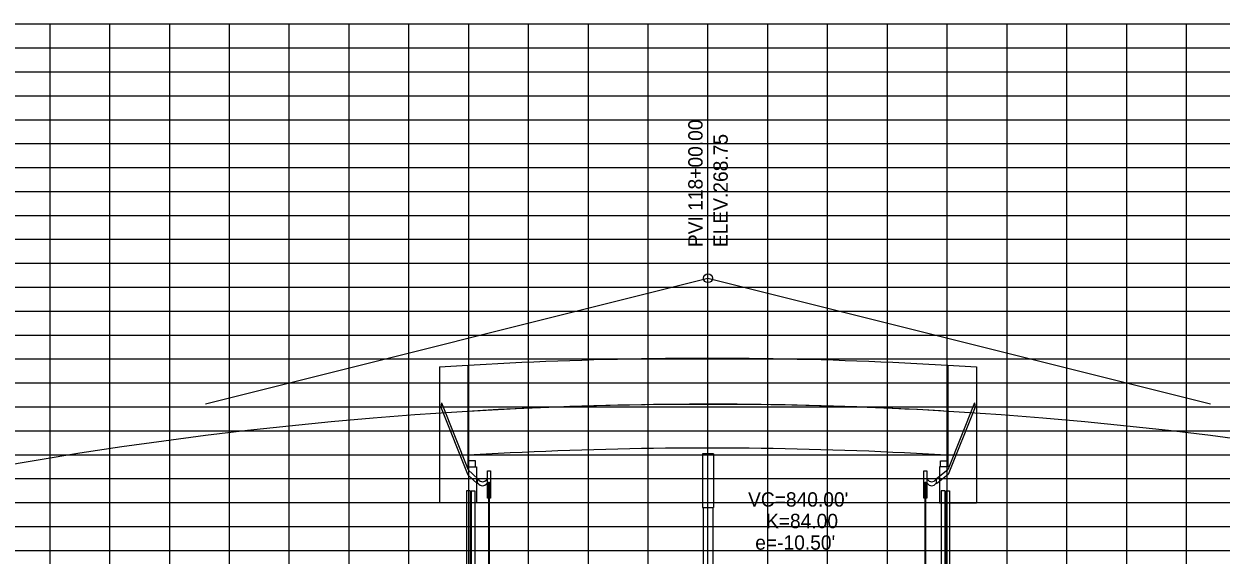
# Model space of a CAD drawing. Extents: x 921603 to 924670, y 1759276 to 1766491.
# Drawn here: x 923154 to 923654, y 1765310 to 1765532 of the extents above; entities that cross this region are included whole.
import ezdxf

# ---------------------------------------------------------------- set-up
doc = ezdxf.new("R2010")
doc.units = 0
for name, color, linetype in [('B-Gen-Exist', 7, 'Continuous'), ('B-Gen-Hidden', 7, 'Continuous'), ('B-Gen-Object', 7, 'Continuous'), ('B-Sub-Retaining Wall', 7, 'Continuous'), ('R_Grid', 7, 'Continuous'), ('R_Grid_Minor', 7, 'Continuous'), ('R_Vert Alg', 7, 'Continuous'), ('R_Vert Alg Annot', 7, 'Continuous')]:
    doc.layers.add(name, color=color, linetype=linetype)

msp = doc.modelspace()

# ---------------------------------------------------------------- linework, layer by layer
at = {"layer": 'B-Gen-Exist'}
for p, q in [((923339.69, 1765389.67), (923339.69, 1765368.36)), ((923539.97, 1765389.68), (923539.97, 1765378.37))]:
    msp.add_line(p, q, dxfattribs=at)
at = {"layer": 'B-Gen-Hidden'}
for p, q in [((923340.35, 1765337.18), (923338.85, 1765337.18)), ((923338.85, 1765337.18), (923338.85, 1765087.18)), ((923340.35, 1765337.18), (923340.35, 1765087.18)), ((923340.85, 1765337.18), (923340.85, 1765087.18)), ((923340.85, 1765337.18), (923342.35, 1765337.18)), ((923342.35, 1765337.18), (923342.35, 1765087.18)), ((923538.8, 1765337.18), (923537.3, 1765337.18)), ((923537.3, 1765337.18), (923537.3, 1765087.18)), ((923538.8, 1765337.18), (923538.8, 1765087.18)), ((923539.3, 1765337.18), (923539.3, 1765087.18)), ((923539.3, 1765337.18), (923540.8, 1765337.18)), ((923540.8, 1765337.18), (923540.8, 1765087.18))]:
    msp.add_line(p, q, dxfattribs=at)
at = {"layer": 'B-Gen-Object'}
for p, q in [((923327.6, 1765388.93), (923337.04, 1765389.52)), ((923337.04, 1765389.52), (923339.6, 1765389.67)), ((923339.6, 1765347.18), (923339.6, 1765389.67)), ((923339.77, 1765389.68), (923342.04, 1765389.82)), ((923339.77, 1765389.68), (923339.77, 1765352.18)), ((923342.04, 1765389.82), (923347.04, 1765390.1)), ((923347.05, 1765390.1), (923352.05, 1765390.37)), ((923352.05, 1765390.37), (923357.05, 1765390.62)), ((923357.05, 1765390.62), (923362.05, 1765390.86)), ((923362.05, 1765390.86), (923367.05, 1765391.08)), ((923367.05, 1765391.08), (923372.05, 1765391.29)), ((923372.05, 1765391.29), (923377.05, 1765391.49)), ((923377.06, 1765391.49), (923382.06, 1765391.67)), ((923382.06, 1765391.67), (923387.06, 1765391.83)), ((923387.06, 1765391.83), (923392.06, 1765391.98)), ((923392.06, 1765391.98), (923397.06, 1765392.12)), ((923397.06, 1765392.12), (923402.06, 1765392.24)), ((923402.07, 1765392.24), (923407.07, 1765392.34)), ((923407.07, 1765392.34), (923412.07, 1765392.43)), ((923412.07, 1765392.43), (923417.07, 1765392.51)), ((923417.07, 1765392.51), (923422.07, 1765392.57)), ((923422.07, 1765392.57), (923427.07, 1765392.61)), ((923427.07, 1765392.61), (923432.07, 1765392.64)), ((923432.08, 1765392.64), (923437.08, 1765392.66)), ((923437.08, 1765392.66), (923442.08, 1765392.66)), ((923442.08, 1765392.66), (923447.08, 1765392.64)), ((923447.08, 1765392.64), (923452.08, 1765392.62)), ((923452.08, 1765392.62), (923457.08, 1765392.57)), ((923457.08, 1765392.57), (923462.08, 1765392.51)), ((923462.09, 1765392.51), (923467.09, 1765392.44)), ((923467.09, 1765392.44), (923472.09, 1765392.35)), ((923472.09, 1765392.35), (923477.09, 1765392.25)), ((923477.09, 1765392.25), (923482.09, 1765392.13)), ((923482.09, 1765392.13), (923487.09, 1765392)), ((923487.1, 1765392), (923492.1, 1765391.85)), ((923492.1, 1765391.85), (923497.1, 1765391.68)), ((923497.1, 1765391.68), (923502.1, 1765391.51)), ((923502.1, 1765391.51), (923507.1, 1765391.31)), ((923507.1, 1765391.31), (923512.1, 1765391.11)), ((923512.1, 1765391.11), (923517.1, 1765390.88)), ((923517.11, 1765390.88), (923522.11, 1765390.65)), ((923522.11, 1765390.65), (923527.11, 1765390.39)), ((923527.11, 1765390.39), (923532.11, 1765390.13)), ((923532.11, 1765390.13), (923539.88, 1765389.69)), ((923539.88, 1765389.69), (923539.88, 1765352.18)), ((923540.05, 1765389.68), (923552.05, 1765389)), ((923540.05, 1765389.68), (923540.05, 1765347.18)), ((923327.6, 1765388.93), (923327.6, 1765332.18)), ((923552.05, 1765389), (923552.05, 1765332.18)), ((923328.39, 1765373.96), (923328.2, 1765372.1)), ((923328.2, 1765372.1), (923339.48, 1765343.9)), ((923328.39, 1765373.96), (923339.6, 1765345.93)), ((923339.77, 1765370.51), (923342.09, 1765370.65)), ((923342.09, 1765370.65), (923347.09, 1765370.93)), ((923347.09, 1765370.93), (923352.09, 1765371.2)), ((923352.09, 1765371.2), (923357.09, 1765371.46)), ((923357.09, 1765371.46), (923362.09, 1765371.69)), ((923362.09, 1765371.69), (923367.08, 1765371.92)), ((923367.08, 1765371.92), (923372.08, 1765372.13)), ((923372.08, 1765372.13), (923377.08, 1765372.32)), ((923377.08, 1765372.32), (923382.08, 1765372.5)), ((923382.08, 1765372.5), (923387.08, 1765372.67)), ((923387.08, 1765372.67), (923392.08, 1765372.81)), ((923392.08, 1765372.81), (923397.08, 1765372.95)), ((923397.08, 1765372.95), (923402.08, 1765373.07)), ((923402.08, 1765373.07), (923407.08, 1765373.17)), ((923407.08, 1765373.17), (923412.08, 1765373.26)), ((923412.08, 1765373.26), (923417.08, 1765373.34)), ((923417.08, 1765373.34), (923422.08, 1765373.4)), ((923422.08, 1765373.4), (923427.08, 1765373.44)), ((923427.08, 1765373.44), (923432.08, 1765373.48)), ((923432.08, 1765373.48), (923437.08, 1765373.49)), ((923437.08, 1765373.49), (923442.08, 1765373.49)), ((923442.08, 1765373.49), (923447.08, 1765373.48)), ((923447.08, 1765373.48), (923452.08, 1765373.45)), ((923452.08, 1765373.45), (923457.08, 1765373.4)), ((923457.08, 1765373.4), (923462.08, 1765373.35)), ((923462.08, 1765373.35), (923467.07, 1765373.27)), ((923467.07, 1765373.27), (923472.07, 1765373.18)), ((923472.07, 1765373.18), (923477.07, 1765373.08)), ((923477.07, 1765373.08), (923482.07, 1765372.96)), ((923482.07, 1765372.96), (923487.07, 1765372.83)), ((923487.07, 1765372.83), (923492.07, 1765372.68)), ((923492.07, 1765372.68), (923497.07, 1765372.52)), ((923497.07, 1765372.52), (923502.07, 1765372.34)), ((923502.07, 1765372.34), (923507.07, 1765372.15)), ((923507.07, 1765372.15), (923512.07, 1765371.94)), ((923512.07, 1765371.94), (923517.07, 1765371.72)), ((923517.07, 1765371.72), (923522.07, 1765371.48)), ((923522.07, 1765371.48), (923527.07, 1765371.23)), ((923527.07, 1765371.23), (923532.07, 1765370.96)), ((923532.07, 1765370.96), (923537.07, 1765370.68)), ((923537.07, 1765370.68), (923539.88, 1765370.51)), ((923551.27, 1765373.96), (923540.05, 1765345.93)), ((923551.45, 1765372.1), (923540.18, 1765343.92)), ((923551.27, 1765373.96), (923551.45, 1765372.1)), ((923342.6, 1765349.68), (923339.6, 1765349.68)), ((923342.6, 1765347.18), (923342.6, 1765349.68)), ((923442.08, 1765352.66), (923437.58, 1765352.66)), ((923437.58, 1765352.66), (923437.58, 1765330.16)), ((923442.08, 1765352.66), (923442.08, 1765330.16)), ((923537.05, 1765347.18), (923537.05, 1765349.68)), ((923537.05, 1765349.68), (923540.05, 1765349.68)), ((923339.6, 1765347.18), (923343.1, 1765347.18)), ((923339.6, 1765345.93), (923343.6, 1765342.18)), ((923343.1, 1765347.18), (923343.1, 1765332.18)), ((923540.05, 1765345.93), (923535.31, 1765342.18)), ((923540.05, 1765347.18), (923536.55, 1765347.18)), ((923536.55, 1765347.18), (923536.55, 1765332.18)), ((923339.48, 1765343.9), (923343.52, 1765340.14)), ((923343.52, 1765340.14), (923343.52, 1765342.25)), ((923540.18, 1765343.92), (923535.31, 1765340.07)), ((923535.31, 1765340.07), (923535.31, 1765342.18)), ((923343.1, 1765332.18), (923327.6, 1765332.18)), ((923437.58, 1765330.16), (923442.08, 1765330.16)), ((923437.83, 1765330.16), (923437.83, 1765282.66)), ((923441.84, 1765330.16), (923441.84, 1765282.66)), ((923536.55, 1765332.18), (923552.05, 1765332.18))]:
    msp.add_line(p, q, dxfattribs=at)
msp.add_lwpolyline([(923339.77, 1765352.18), (923342.13, 1765352.32), (923347.13, 1765352.6), (923352.12, 1765352.87), (923357.12, 1765353.12), (923362.12, 1765353.36), (923367.12, 1765353.59), (923372.11, 1765353.79), (923377.11, 1765353.99), (923382.11, 1765354.17), (923387.11, 1765354.33), (923392.1, 1765354.48), (923397.1, 1765354.62), (923402.1, 1765354.74), (923407.1, 1765354.84), (923412.09, 1765354.93), (923417.09, 1765355.01), (923422.09, 1765355.07), (923427.08, 1765355.11), (923432.08, 1765355.14), (923437.08, 1765355.16), (923442.08, 1765355.16), (923447.07, 1765355.14), (923452.07, 1765355.12), (923457.07, 1765355.07), (923462.07, 1765355.01), (923467.06, 1765354.94), (923472.06, 1765354.85), (923477.06, 1765354.75), (923482.06, 1765354.63), (923487.05, 1765354.5), (923492.05, 1765354.35), (923497.05, 1765354.18), (923502.04, 1765354.01), (923507.04, 1765353.81), (923512.04, 1765353.61), (923517.04, 1765353.38), (923522.03, 1765353.15), (923527.03, 1765352.9), (923532.03, 1765352.63), (923537.03, 1765352.35), (923539.88, 1765352.18)], dxfattribs=at)
for centre, major_axis, start_param, end_param in [((923337.08, 1765374.52), (0, 15), 0.011919, 0.012542), ((923342.08, 1765374.82), (0, 15), 0.011334, 0.011919), ((923347.08, 1765375.1), (0, 15), 0.010748, 0.011334), ((923352.08, 1765375.37), (0, 15), 0.010165, 0.010748), ((923357.08, 1765375.62), (0, 15), 0.009541, 0.010165), ((923362.08, 1765375.86), (0, 15), 0.008951, 0.009541), ((923367.08, 1765376.08), (0, 15), 0.008364, 0.008951), ((923372.08, 1765376.29), (0, 15), 0.007778, 0.008364), ((923377.08, 1765376.49), (0, 15), 0.007172, 0.007778), ((923382.08, 1765376.67), (0, 15), 0.006567, 0.007172), ((923387.08, 1765376.83), (0, 15), 0.005981, 0.006567), ((923392.08, 1765376.98), (0, 15), 0.005394, 0.005981), ((923397.08, 1765377.12), (0, 15), 0.004804, 0.005394), ((923402.08, 1765377.24), (0, 15), 0.00418, 0.004804), ((923407.08, 1765377.34), (0, 15), 0.003597, 0.00418), ((923412.08, 1765377.43), (0, 15), 0.003011, 0.003597), ((923417.08, 1765377.51), (0, 15), 0.002426, 0.003011), ((923422.08, 1765377.57), (0, 15), 0.001802, 0.002426), ((923427.08, 1765377.61), (0, 15), 0.001214, 0.001802), ((923432.08, 1765377.64), (0, 15), 0.000627, 0.001214), ((923437.08, 1765377.66), (0, 15), 0.000041, 0.000627), ((923442.08, 1765377.66), (0, 15), 6.282617, 6.283226), ((923447.08, 1765377.64), (0, 15), 6.282015, 6.282617), ((923452.08, 1765377.62), (0, 15), 6.281429, 6.282015), ((923457.08, 1765377.57), (0, 15), 6.280842, 6.281429), ((923462.08, 1765377.51), (0, 15), 6.280245, 6.280842), ((923467.08, 1765377.44), (0, 15), 6.279632, 6.280245), ((923472.08, 1765377.35), (0, 15), 6.279045, 6.279632), ((923477.08, 1765377.25), (0, 15), 6.278459, 6.279045), ((923482.08, 1765377.13), (0, 15), 6.277872, 6.278459), ((923487.08, 1765377), (0, 15), 6.277248, 6.277872), ((923492.08, 1765376.85), (0, 15), 6.276662, 6.277248), ((923497.08, 1765376.68), (0, 15), 6.276075, 6.276662), ((923502.08, 1765376.51), (0, 15), 6.275489, 6.276075), ((923507.08, 1765376.31), (0, 15), 6.274876, 6.275489), ((923512.08, 1765376.11), (0, 15), 6.274278, 6.274876), ((923517.08, 1765375.88), (0, 15), 6.273692, 6.274278), ((923522.08, 1765375.65), (0, 15), 6.273106, 6.273692), ((923527.08, 1765375.39), (0, 15), 6.272504, 6.273106), ((923532.08, 1765375.13), (0, 15), 6.271895, 6.272504), ((923345.6, 1765381.55), (0, 42.29), 2.892883, 3.380307), ((923345.6, 1765381.55), (0, 40.62), 2.892883, 3.390303), ((923533.31, 1765381.55), (0, -40.62), 6.034475, 6.531895), ((923533.31, 1765381.55), (0, -42.29), 6.044471, 6.521899)]:
    msp.add_ellipse(centre, major_axis=major_axis, ratio=0.2, start_param=start_param, end_param=end_param, dxfattribs=at)
at = {"layer": 'B-Sub-Retaining Wall'}
for p, q in [((923347.6, 1765334.08), (923347.6, 1765345.51)), ((923347.6, 1765345.51), (923348.94, 1765345.51)), ((923348.94, 1765345.51), (923348.94, 1765334.08)), ((923529.98, 1765345.51), (923531.31, 1765345.51)), ((923529.98, 1765334.08), (923529.98, 1765345.51)), ((923531.31, 1765345.51), (923531.31, 1765334.08)), ((923348.02, 1765334.08), (923348.02, 1765340.75)), ((923348.02, 1765340.75), (923348.52, 1765340.75)), ((923348.52, 1765334.08), (923348.52, 1765340.75)), ((923530.4, 1765334.08), (923530.4, 1765340.75)), ((923530.4, 1765340.75), (923530.9, 1765340.75)), ((923530.9, 1765334.08), (923530.9, 1765340.75)), ((923348.02, 1765334.08), (923347.6, 1765334.08)), ((923348.02, 1765334.08), (923348.02, 1765230.99)), ((923348.52, 1765230.99), (923348.52, 1765334.08)), ((923348.94, 1765334.08), (923348.52, 1765334.08)), ((923530.4, 1765334.08), (923529.98, 1765334.08)), ((923530.4, 1765334.08), (923530.4, 1765230.99)), ((923530.9, 1765230.99), (923530.9, 1765334.08)), ((923531.31, 1765334.08), (923530.9, 1765334.08))]:
    msp.add_line(p, q, dxfattribs=at)
at = {"layer": 'R_Grid'}
for p, q in [((921639.83, 1765532.26), (924639.83, 1765532.26)), ((921639.83, 1765532.26), (924639.83, 1765532.26)), ((923239.83, 1764932.26), (923239.83, 1765532.26)), ((923339.83, 1764932.26), (923339.83, 1765532.26)), ((923439.83, 1764932.26), (923439.83, 1765532.26)), ((923539.83, 1764932.26), (923539.83, 1765532.26)), ((923639.83, 1764932.26), (923639.83, 1765532.26)), ((921639.83, 1765482.26), (924639.83, 1765482.26)), ((921639.83, 1765432.26), (924639.83, 1765432.26)), ((921639.83, 1765382.26), (924639.83, 1765382.26)), ((921639.83, 1765332.26), (924639.83, 1765332.26))]:
    msp.add_line(p, q, dxfattribs=at)
at = {"layer": 'R_Grid_Minor'}
for p, q in [((923164.83, 1764932.26), (923164.83, 1765532.26)), ((923189.83, 1764932.26), (923189.83, 1765532.26)), ((923214.83, 1764932.26), (923214.83, 1765532.26)), ((923264.83, 1764932.26), (923264.83, 1765532.26)), ((923289.83, 1764932.26), (923289.83, 1765532.26)), ((923314.83, 1764932.26), (923314.83, 1765532.26)), ((923364.83, 1764932.26), (923364.83, 1765532.26)), ((923389.83, 1764932.26), (923389.83, 1765532.26)), ((923414.83, 1764932.26), (923414.83, 1765532.26)), ((923464.83, 1764932.26), (923464.83, 1765532.26)), ((923489.83, 1764932.26), (923489.83, 1765532.26)), ((923514.83, 1764932.26), (923514.83, 1765532.26)), ((923564.83, 1764932.26), (923564.83, 1765532.26)), ((923589.83, 1764932.26), (923589.83, 1765532.26)), ((923614.83, 1764932.26), (923614.83, 1765532.26)), ((921639.83, 1765522.26), (924639.83, 1765522.26)), ((921639.83, 1765512.26), (924639.83, 1765512.26)), ((921639.83, 1765502.26), (924639.83, 1765502.26)), ((921639.83, 1765492.26), (924639.83, 1765492.26)), ((921639.83, 1765472.26), (924639.83, 1765472.26)), ((921639.83, 1765462.26), (924639.83, 1765462.26)), ((921639.83, 1765452.26), (924639.83, 1765452.26)), ((921639.83, 1765442.26), (924639.83, 1765442.26)), ((921639.83, 1765422.26), (924639.83, 1765422.26)), ((921639.83, 1765412.26), (924639.83, 1765412.26)), ((921639.83, 1765402.26), (924639.83, 1765402.26)), ((921639.83, 1765392.26), (924639.83, 1765392.26)), ((921639.83, 1765372.26), (924639.83, 1765372.26)), ((921639.83, 1765362.26), (924639.83, 1765362.26)), ((921639.83, 1765352.26), (924639.83, 1765352.26)), ((921639.83, 1765342.26), (924639.83, 1765342.26)), ((921639.83, 1765322.26), (924639.83, 1765322.26)), ((921639.83, 1765312.26), (924639.83, 1765312.26))]:
    msp.add_line(p, q, dxfattribs=at)
at = {"layer": 'R_Vert Alg'}
msp.add_lwpolyline([(923142.33, 1765347.17), (923159.83, 1765350.18), (923177.33, 1765353), (923194.83, 1765355.64), (923212.33, 1765358.11), (923229.83, 1765360.38), (923247.33, 1765362.48), (923264.83, 1765364.39), (923282.33, 1765366.13), (923299.83, 1765367.68), (923317.33, 1765369.04), (923334.83, 1765370.23), (923352.33, 1765371.23), (923369.83, 1765372.05), (923387.33, 1765372.69), (923404.83, 1765373.14), (923422.33, 1765373.42), (923457.33, 1765373.42), (923474.83, 1765373.14), (923492.33, 1765372.69), (923509.83, 1765372.05), (923527.33, 1765371.23), (923544.83, 1765370.23), (923562.33, 1765369.04), (923579.83, 1765367.68), (923597.33, 1765366.13), (923614.83, 1765364.39), (923632.33, 1765362.48), (923649.83, 1765360.38), (923667.33, 1765358.11)], dxfattribs=at)
at = {"layer": 'R_Vert Alg Annot'}
for p, q in [((923439.83, 1765436.01), (923439.83, 1765520.01)), ((923439.83, 1765426.01), (923439.83, 1765436.01)), ((923229.83, 1765373.51), (923439.83, 1765426.01)), ((923439.83, 1765426.01), (923649.83, 1765373.51))]:
    msp.add_line(p, q, dxfattribs=at)
msp.add_circle((923439.83, 1765426.01), 1.85, dxfattribs=at)

# ---------------------------------------------------------------- texts
for s, p in [('PVI 118+00.00', (923437.58, 1765439.01)), ('ELEV.268.75', (923448.08, 1765439.01))]:
    msp.add_text(s, height=6, rotation=90, dxfattribs=at).set_placement(p)
for s, p in [("VC=840.00'", (923456.57, 1765330.56)), ('K=84.00', (923464.06, 1765321.56)), ("e=-10.50'", (923459.57, 1765312.56))]:
    msp.add_text(s, height=6, dxfattribs=at).set_placement(p)

doc.saveas('drawing.dxf')
